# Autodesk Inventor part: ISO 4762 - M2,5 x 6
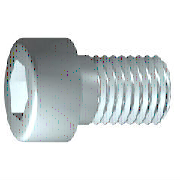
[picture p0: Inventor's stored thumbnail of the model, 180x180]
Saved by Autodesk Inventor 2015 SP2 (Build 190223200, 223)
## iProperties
Created: 2012-02
Part Number: ISO 4762 - M2,5 x 6
Material: Stainless Steel, 440C
Description: Hexagon Socket Head Cap Screw
Document SubType Name: Modeling
Standard: ISO 4762
Designer: rYan
Standard Revision: Fourth edition 2004-03-01
Standards Organization: ISO
Language: en-US
Size Designation: M2,5 x 6
Categories: <MemberInstance><Categories><Category DisplayName="Fasteners" InternalName="e4da775c-781d-43d5-af7c-5136215cf5a6" Mnemonic="FSTN"><Category DisplayName="Bolts"
Density: 7.75 g/cm^3
Appearance: Halbpoliert
IsCustomPart: 0
Author: rYan
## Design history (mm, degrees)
sketch "Sketch1"
  geometry: L1 (-0.733, 0)-(6, 0); L2 (6, 0)-(6, 1.25); L3 (6, 1.25)-(1.125, 1.25); L4 (1.125, 1.25)-(0.849, 1.25); L5 (0.849, 1.25)-(0, 1.25); L6 (0, 1.25)-(0, 2.25); L7 (0, 2.25)-(-2.5, 2.25); L8 (-2.5, 2.25)-(-2.5, 1.155); L9 (-2.5, 1.155)-(-1.4, 1.155); L10 (-1.4, 1.155)-(-0.733, 0); L11 (-4.2, 0)-(7.7, 0) reference; L12 (0, -0.45)-(0, 2.7) reference; L13 (1.125, 1.25)-(0, 1.25)
  constraints: 22 end point, 6 parallel, 2 collinear, 2 perpendicular, 1 horizontal, 1 point on line
  dimensions: "d1" = 4.875 distance from line of L3.end L2 (= GEL); "d2" = 0.27615 distance of L4.end L3.end (computed from GAL); "d3" = 2.5 distance between parallel lines of L8 L6 (= KOH); "d4" = 1.1 distance of L8.end L9.end (= INTI); "d5" = 60 deg angle of L10 L1; "d6" = 2.5 diameter of L3 L1 (= GD); "d7" = 2.5 diameter of L5 L1 (= BDM); "d8" = 2.3094 diameter of L9 L1 (= 1.1547 x SW); "d9" = 4.5 diameter of L7 L1 (= KOD); "d26" = 6 distance between parallel lines of L12 L2 (= NLG)
revolve "Body" sketch "Sketch1" stored, may be unused: angle "d10" = 90 deg
sketch "Sketch2"
  geometry: L1 (0, -3.15)-(0, 3.15) reference; L2 (-3.15, 0)-(3.15, 0) reference; L3 (1.155, 0)-(0.577, -1); L4 (0.577, -1)-(-0.577, -1); L5 (-0.577, -1)-(-1.155, 0); L6 (-1.155, 0)-(-0.577, 1); L7 (-0.577, 1)-(0.577, 1); L8 (0.577, 1)-(1.155, 0); 2 further points
  constraints: 12 end point, 1 coincident, 1 horizontal alignment, 1 point on line, 12 other
extrude "Slot" join sketch "Sketch2" stored distance "d11" = 10; taper "d12" = 0 deg
fillet "Fillet1" dims "d17" = 0.25 (= RR)
feature "Thread" dims "d13" = 4.875 (= GEL), "d14" = 0
chamfer "Chamfer1" distance "d15" = 0.27605 (= -0.5 x SPD + 0.5 x GD); stored, may be unused: second distance "d16" = 0.27605 (= GUL), angle "d27" = 45 deg
workplane "Work Plane1"
fillet "Fillet2" dims "d30" = 0.1 (= R)
body "Solid1"
other parameters: "GD" = 2.5 [user parameter; used in 2 equation terms], "NLG" = 6 [user parameter; used in 1 equation term], "GEL" = 4.875 [user parameter; used in 2 equation terms], "KOD" = 4.5 [user parameter; used in 1 equation term], "KOH" = 2.5 [user parameter; used in 1 equation term], "INTI" = 1.1 [user parameter; used in 1 equation term], "GAL" = 0.27605 (= 0.61345 x PTC) [user parameter; used in 1 equation term], "GUL" = 0.27605 (= 0.61345 x PTC) [user parameter; used in 1 equation term], "BDM" = 2.5 (= NND) [user parameter; used in 1 equation term], "SW" = 2 [user parameter; used in 2 equation terms], "RR" = 0.25 [user parameter; used in 1 equation term], "SPD" = 1.94789 (= NND - 1.2269 x PTC) [user parameter; used in 1 equation term], "d19" = 0, "d28" = 0, "d29" = 0, "R" = 0.1 [user parameter; used in 1 equation term], "TOA" = 30 deg [user parameter], "GD1" = 1.94789 (= THREADDIA - 1.2269 x PTC) [user parameter], "THREADDIA" = 2.5 [user parameter; used in 1 equation term], "FAWI" = 45 deg [user parameter], "TPU" = 22.22222 (computed from PTC) [user parameter], "PTC" = 0.45 [user parameter; used in 5 equation terms], "NND" = 2.5 [user parameter; used in 2 equation terms], "E0" = 2.31 (= 1.155 x SW) [user parameter]
